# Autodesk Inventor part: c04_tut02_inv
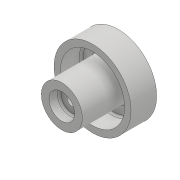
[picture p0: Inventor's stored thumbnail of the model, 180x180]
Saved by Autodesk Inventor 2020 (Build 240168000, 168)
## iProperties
Created: 2017-04
Part Number: c04_tut02_inv
Material: Generic
Document SubType Name: Modeling
Designer: CADCIM 00
Density: 1 g/cm^3
Appearance: Default
Author: CADCIM 00
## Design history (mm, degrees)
sketch "Sketch1"
  geometry: L1 (0, 0)-(-22, 0); L2 (-22, 0)-(-22, 4); L3 (-22, 4)-(-36, 4); L4 (-36, 4)-(-36, 8.5); L5 (-37.5, 10)-(-44, 10); L6 (-44, 10)-(-44, 16); L7 (-44, 16)-(-5.5, 16); L8 (-4, 17.5)-(-4, 23.5); L9 (-5.5, 25)-(-20, 25); L10 (-20, 25)-(-20, 30); L11 (-20, 30)-(0, 30); L12 (0, 30)-(0, 0); A1 r 1.5 centre (-5.5, 23.5) between (-4, 23.5) and (-5.5, 25); A2 r 1.5 centre (-37.5, 8.5) between (-36, 8.5) and (-37.5, 10); A3 r 1.5 centre (-5.5, 17.5) between (-5.5, 16) and (-4, 17.5)
  constraints: 24 end point, 11 perpendicular, 6 point on circle, 6 tangent, 3 centre point, 2 equal radius, 1 horizontal
  dimensions: "d0" = 8 diameter of L3 L1; "d1" = 20 diameter of L5 L1; "d2" = 32 diameter of L7 L1; "d3" = 50 diameter of L9 L1; "d4" = 60 diameter of L11 L1; "d5" = 4 distance between parallel lines of L8 L12; "d6" = 20 distance of L10.end L11.end; "d7" = 22 distance of L1.start L1.end; "d9" = 36 distance between parallel lines of L4 L12; "d10" = 44 distance between parallel lines of L12 L6; "d11" = 1.5 radius of A1
revolve "Revolution1" sketch "Sketch1" stored, may be unused: angle "d12" = 90 deg
body "Solid1"
